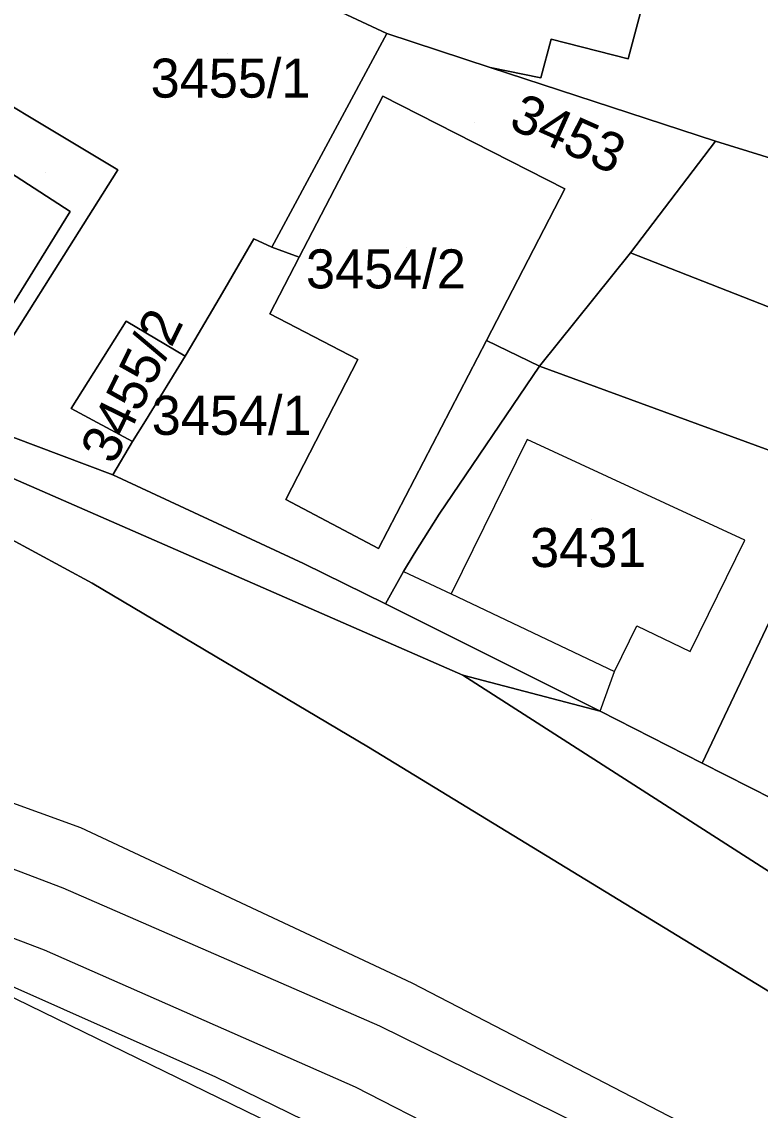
# Model space of a CAD drawing. Extents: x -262657 to -261595, y -1238015 to -1237156.
# Drawn here: x -262186.5 to -262148.7, y -1237601.5 to -1237545.8 of the extents above; entities that cross this region are included whole.
import ezdxf

# ---------------------------------------------------------------- set-up
doc = ezdxf.new("R2010")
doc.units = 0
for name, color, linetype in [('body_kn', 7, 'Continuous'), ('kladpar_druhypozemkov', 7, 'Continuous'), ('kladpar_hranice', 7, 'Continuous'), ('kladpar_parcelnecisla', 7, 'Continuous'), ('kladpar_plochy', 7, 'Continuous'), ('zappar_hrandruhpozemk', 7, 'Continuous')]:
    doc.layers.add(name, color=color, linetype=linetype)

msp = doc.modelspace()

# ---------------------------------------------------------------- linework, layer by layer
at = {"layer": 'body_kn'}
for p, q in [((-262167.81, -1237546.39), (-262167.81, -1237546.39)), ((-262167.81, -1237546.39), (-262167.81, -1237546.39)), ((-262159.39, -1237546.68), (-262159.39, -1237546.68)), ((-262155.46, -1237547.69), (-262155.46, -1237547.69)), ((-262162.52, -1237548.12), (-262162.52, -1237548.12)), ((-262159.92, -1237548.65), (-262159.92, -1237548.65)), ((-262168.02, -1237549.6), (-262168.02, -1237549.6)), ((-262150.98, -1237551.9), (-262150.98, -1237551.9)), ((-262150.98, -1237551.9), (-262150.98, -1237551.9)), ((-262181.58, -1237553.36), (-262181.58, -1237553.36)), ((-262158.69, -1237554.34), (-262158.69, -1237554.34)), ((-262184.02, -1237555.5), (-262184.02, -1237555.5)), ((-262174.62, -1237556.9), (-262174.62, -1237556.9)), ((-262173.7, -1237557.32), (-262173.7, -1237557.32)), ((-262172.3, -1237557.84), (-262172.3, -1237557.84)), ((-262155.34, -1237557.61), (-262155.34, -1237557.61)), ((-262176.21, -1237559.66), (-262176.21, -1237559.66)), ((-262173.8, -1237560.75), (-262173.8, -1237560.75)), ((-262173.8, -1237560.75), (-262173.8, -1237560.75)), ((-262181.14, -1237561.11), (-262181.14, -1237561.11)), ((-262177.64, -1237562.07), (-262177.64, -1237562.07)), ((-262162.71, -1237562.1), (-262162.71, -1237562.1)), ((-262178.13, -1237562.91), (-262178.13, -1237562.91)), ((-262169.29, -1237563.08), (-262169.29, -1237563.08)), ((-262159.99, -1237563.42), (-262159.99, -1237563.42)), ((-262159.99, -1237563.42), (-262159.99, -1237563.42)), ((-262183.96, -1237565.59), (-262183.96, -1237565.59)), ((-262180.16, -1237566.22), (-262180.16, -1237566.22)), ((-262180.82, -1237567.28), (-262180.82, -1237567.28)), ((-262180.82, -1237567.28), (-262180.82, -1237567.28)), ((-262160.62, -1237567.18), (-262160.62, -1237567.18)), ((-262181.83, -1237568.98), (-262181.83, -1237568.98)), ((-262181.83, -1237568.98), (-262181.83, -1237568.98)), ((-262172.98, -1237570.25), (-262172.98, -1237570.25)), ((-262165.13, -1237571), (-262165.13, -1237571)), ((-262149.48, -1237572.34), (-262149.48, -1237572.34)), ((-262168.23, -1237572.76), (-262168.23, -1237572.76)), ((-262166.4, -1237573.04), (-262166.4, -1237573.04)), ((-262172.07, -1237573.52), (-262172.07, -1237573.52)), ((-262172.07, -1237573.52), (-262172.07, -1237573.52)), ((-262166.95, -1237573.93), (-262166.95, -1237573.93)), ((-262166.95, -1237573.93), (-262166.95, -1237573.93)), ((-262182.88, -1237574.53), (-262182.88, -1237574.53)), ((-262164.52, -1237575.08), (-262164.52, -1237575.08)), ((-262164.52, -1237575.08), (-262164.52, -1237575.08)), ((-262167.88, -1237575.6), (-262167.88, -1237575.6)), ((-262155.02, -1237576.72), (-262155.02, -1237576.72)), ((-262152.28, -1237578.04), (-262152.28, -1237578.04)), ((-262156.15, -1237579.06), (-262156.15, -1237579.06)), ((-262163.92, -1237579.25), (-262163.92, -1237579.25)), ((-262156.89, -1237581.09), (-262156.89, -1237581.09)), ((-262156.89, -1237581.09), (-262156.89, -1237581.09)), ((-262168.75, -1237582.94), (-262168.75, -1237582.94)), ((-262151.67, -1237583.75), (-262151.67, -1237583.75)), ((-262151.67, -1237583.75), (-262151.67, -1237583.75)), ((-262183.48, -1237587.04), (-262183.48, -1237587.04)), ((-262184.37, -1237590.16), (-262184.37, -1237590.16)), ((-262185.35, -1237593.32), (-262185.35, -1237593.32)), ((-262166.53, -1237595), (-262166.53, -1237595)), ((-262168.16, -1237597.22), (-262168.16, -1237597.22)), ((-262176.55, -1237599.84), (-262176.55, -1237599.84)), ((-262169.42, -1237600.33), (-262169.42, -1237600.33))]:
    msp.add_line(p, q, dxfattribs=at)
at = {"layer": 'kladpar_druhypozemkov'}
for p, q in [((-262175.97, -1237547.4), (-262175.97, -1237547.4)), ((-262163.31, -1237550.96), (-262163.31, -1237550.96)), ((-262185.26, -1237553.48), (-262185.26, -1237553.48)), ((-262166.79, -1237557.34), (-262166.79, -1237557.34)), ((-262181.55, -1237563.61), (-262181.55, -1237563.61)), ((-262175.55, -1237564.94), (-262175.55, -1237564.94)), ((-262157.35, -1237571.27), (-262157.35, -1237571.27))]:
    msp.add_line(p, q, dxfattribs=at)
at = {"layer": 'kladpar_hranice'}
for p, q in [((-262156.89, -1237581.09), (-262163.92, -1237579.25)), ((-262163.92, -1237579.25), (-262156.89, -1237581.09))]:
    msp.add_line(p, q, dxfattribs=at)
for points in [[(-262167.81, -1237546.39), (-262172.13, -1237544.35), (-262172.1, -1237542.37), (-262164.03, -1237540.79), (-262161.8, -1237540.63), (-262154.15, -1237542.73), (-262155.46, -1237547.69), (-262159.39, -1237546.68), (-262159.92, -1237548.65), (-262162.52, -1237548.12), (-262167.81, -1237546.39)], [(-262181.83, -1237568.98), (-262189.59, -1237566.07), (-262181.58, -1237553.36), (-262191.37, -1237547.49), (-262190.39, -1237546.16), (-262190.29, -1237543.75), (-262185.04, -1237542.92), (-262172.97, -1237543.92), (-262172.13, -1237544.35), (-262167.81, -1237546.39), (-262173.7, -1237557.32), (-262174.62, -1237556.9), (-262176.21, -1237559.66), (-262177.64, -1237562.07), (-262178.13, -1237562.91), (-262181.14, -1237561.11), (-262183.96, -1237565.59), (-262180.82, -1237567.28), (-262181.83, -1237568.98)], [(-262150.98, -1237551.9), (-262162.52, -1237548.12), (-262159.92, -1237548.65), (-262159.39, -1237546.68), (-262155.46, -1237547.69), (-262154.15, -1237542.73), (-262146.14, -1237544.88), (-262127.87, -1237550.65), (-262129.29, -1237557.12), (-262089.88, -1237572.05), (-262091.36, -1237573.71), (-262114.93, -1237564.15), (-262131.62, -1237558.35), (-262139.63, -1237555.56), (-262146.25, -1237553.37), (-262150.98, -1237551.9)], [(-262159.99, -1237563.42), (-262162.71, -1237562.1), (-262158.69, -1237554.34), (-262168.02, -1237549.6), (-262172.3, -1237557.84), (-262173.7, -1237557.32), (-262167.81, -1237546.39), (-262162.52, -1237548.12), (-262150.98, -1237551.9), (-262155.34, -1237557.61), (-262159.99, -1237563.42)], [(-262189.59, -1237566.07), (-262190.37, -1237565.77), (-262200.33, -1237562.28), (-262199.41, -1237560.7), (-262198.38, -1237559.06), (-262189.46, -1237564.28), (-262184.02, -1237555.5), (-262190.48, -1237551.32), (-262189.4, -1237549.52), (-262191.8, -1237548.08), (-262191.37, -1237547.49), (-262181.58, -1237553.36), (-262189.59, -1237566.07)], [(-262284.57, -1237548.36), (-262280.56, -1237548.52), (-262275.85, -1237548.71), (-262269.47, -1237549.04), (-262241.76, -1237550.48), (-262238.68, -1237550.01), (-262238.76, -1237551.55), (-262233.07, -1237552.83), (-262232.32, -1237553), (-262224.57, -1237554.75), (-262222.49, -1237555.21), (-262210.43, -1237558.79), (-262200.33, -1237562.28), (-262190.37, -1237565.77), (-262189.59, -1237566.07), (-262181.83, -1237568.98), (-262172.07, -1237573.52)], [(-262193.47, -1237551.01), (-262191.8, -1237548.08), (-262189.4, -1237549.52), (-262190.48, -1237551.32), (-262184.02, -1237555.5), (-262189.46, -1237564.28), (-262198.38, -1237559.06), (-262193.47, -1237551.01)], [(-262173.8, -1237560.75), (-262172.3, -1237557.84), (-262168.02, -1237549.6), (-262158.69, -1237554.34), (-262162.71, -1237562.1), (-262168.23, -1237572.76), (-262172.98, -1237570.25), (-262169.29, -1237563.08), (-262173.8, -1237560.75)], [(-262163.92, -1237579.25), (-262199.34, -1237563.75), (-262233.3, -1237554.55), (-262250.47, -1237552.01), (-262250.41, -1237550.47), (-262269.27, -1237550.46)], [(-262269.27, -1237550.46), (-262250.41, -1237550.47), (-262250.47, -1237552.01), (-262233.3, -1237554.55), (-262199.34, -1237563.75), (-262163.92, -1237579.25)], [(-262021.16, -1237749.53), (-262023.07, -1237746.54), (-262062.32, -1237685.22), (-262069, -1237678.62), (-262099.55, -1237648.46), (-262139.84, -1237618.74), (-262199.91, -1237589.44), (-262214.16, -1237582.49), (-262218.71, -1237580.27), (-262317.63, -1237552.02)], [(-262300.35, -1237552.38), (-262266.92, -1237554.73), (-262245.89, -1237556.21), (-262215.1, -1237563.73), (-262191.61, -1237569.82), (-262182.88, -1237574.53), (-262168.75, -1237582.94), (-262143.5, -1237598.35), (-262084.62, -1237634.29), (-262085.82, -1237636.26), (-262084.08, -1237640.44), (-262083.99, -1237644.63), (-262083.24, -1237649.32), (-262080.3, -1237653.05), (-262067.75, -1237663.13)], [(-262134.31, -1237565.86), (-262155.34, -1237557.61), (-262150.98, -1237551.9), (-262146.25, -1237553.37), (-262139.63, -1237555.56), (-262131.62, -1237558.35), (-262134.31, -1237565.86)], [(-262143.5, -1237598.35), (-262168.75, -1237582.94), (-262182.88, -1237574.53), (-262191.61, -1237569.82), (-262215.1, -1237563.73), (-262245.89, -1237556.21), (-262266.92, -1237554.73)], [(-262180.82, -1237567.28), (-262180.16, -1237566.22), (-262178.13, -1237562.91), (-262177.64, -1237562.07), (-262176.21, -1237559.66), (-262174.62, -1237556.9), (-262173.7, -1237557.32), (-262172.3, -1237557.84), (-262173.8, -1237560.75), (-262169.29, -1237563.08), (-262172.98, -1237570.25), (-262168.23, -1237572.76), (-262162.71, -1237562.1), (-262159.99, -1237563.42), (-262165.13, -1237571), (-262166.4, -1237573.04), (-262166.95, -1237573.93), (-262167.88, -1237575.6), (-262172.07, -1237573.52), (-262181.83, -1237568.98), (-262180.82, -1237567.28)], [(-262131.32, -1237572.4), (-262132.54, -1237575.34), (-262139.2, -1237571.87), (-262146.03, -1237568.54), (-262159.99, -1237563.42), (-262155.34, -1237557.61), (-262134.31, -1237565.86), (-262133.96, -1237565.99), (-262135.76, -1237570.66), (-262131.32, -1237572.4)], [(-262180.82, -1237567.28), (-262183.96, -1237565.59), (-262181.14, -1237561.11), (-262178.13, -1237562.91), (-262180.16, -1237566.22), (-262180.82, -1237567.28)], [(-262151.67, -1237583.75), (-262156.89, -1237581.09), (-262167.88, -1237575.6), (-262166.95, -1237573.93), (-262166.4, -1237573.04), (-262165.13, -1237571), (-262159.99, -1237563.42), (-262146.03, -1237568.54), (-262139.2, -1237571.87), (-262132.54, -1237575.34), (-262135.03, -1237578.53), (-262135.63, -1237579.3), (-262141.27, -1237576.56), (-262146.92, -1237573.76), (-262151.67, -1237583.75)], [(-262172.07, -1237573.52), (-262167.88, -1237575.6), (-262156.89, -1237581.09)], [(-262141.98, -1237588.67), (-262151.67, -1237583.75), (-262146.92, -1237573.76), (-262141.27, -1237576.56), (-262135.63, -1237579.3), (-262138.4, -1237583.38), (-262140.61, -1237586.64), (-262141.98, -1237588.67)], [(-262143.5, -1237598.35), (-262144.39, -1237597.16), (-262143.52, -1237592.34), (-262163.92, -1237579.25)], [(-262163.92, -1237579.25), (-262143.52, -1237592.34), (-262144.39, -1237597.16), (-262143.5, -1237598.35)], [(-262156.89, -1237581.09), (-262151.67, -1237583.75), (-262141.98, -1237588.67), (-262129.36, -1237595.54)]]:
    msp.add_lwpolyline(points, dxfattribs=at)
at = {"layer": 'kladpar_plochy'}
for points in [[(-262167.81, -1237546.39), (-262172.13, -1237544.35), (-262172.1, -1237542.37), (-262164.03, -1237540.79), (-262161.8, -1237540.63), (-262154.15, -1237542.73), (-262155.46, -1237547.69), (-262159.39, -1237546.68), (-262159.92, -1237548.65), (-262162.52, -1237548.12)], [(-262181.83, -1237568.98), (-262189.59, -1237566.07), (-262181.58, -1237553.36), (-262191.37, -1237547.49), (-262190.39, -1237546.16), (-262190.29, -1237543.75), (-262185.04, -1237542.92), (-262172.97, -1237543.92), (-262172.13, -1237544.35), (-262167.81, -1237546.39), (-262173.7, -1237557.32), (-262174.62, -1237556.9), (-262176.21, -1237559.66), (-262177.64, -1237562.07), (-262178.13, -1237562.91), (-262181.14, -1237561.11), (-262183.96, -1237565.59), (-262180.82, -1237567.28)], [(-262150.98, -1237551.9), (-262162.52, -1237548.12), (-262159.92, -1237548.65), (-262159.39, -1237546.68), (-262155.46, -1237547.69), (-262154.15, -1237542.73), (-262146.14, -1237544.88), (-262127.87, -1237550.65), (-262129.29, -1237557.12), (-262089.88, -1237572.05), (-262091.36, -1237573.71), (-262114.93, -1237564.15), (-262131.62, -1237558.35), (-262139.63, -1237555.56), (-262146.25, -1237553.37)], [(-262159.99, -1237563.42), (-262162.71, -1237562.1), (-262158.69, -1237554.34), (-262168.02, -1237549.6), (-262172.3, -1237557.84), (-262173.7, -1237557.32), (-262167.81, -1237546.39), (-262162.52, -1237548.12), (-262150.98, -1237551.9), (-262155.34, -1237557.61)], [(-262269.27, -1237550.46), (-262250.41, -1237550.47), (-262250.47, -1237552.01), (-262233.3, -1237554.55), (-262199.34, -1237563.75), (-262163.92, -1237579.25), (-262143.52, -1237592.34), (-262144.39, -1237597.16), (-262143.5, -1237598.35), (-262168.75, -1237582.94), (-262182.88, -1237574.53), (-262191.61, -1237569.82), (-262215.1, -1237563.73), (-262245.89, -1237556.21), (-262266.92, -1237554.73), (-262290.64, -1237551.94), (-262300.35, -1237552.38), (-262305.92, -1237551.99), (-262307.78, -1237550.29), (-262309.76, -1237547.34), (-262302.19, -1237547.65), (-262284.57, -1237548.36)], [(-262189.59, -1237566.07), (-262190.37, -1237565.77), (-262200.33, -1237562.28), (-262199.41, -1237560.7), (-262198.38, -1237559.06), (-262189.46, -1237564.28), (-262184.02, -1237555.5), (-262190.48, -1237551.32), (-262189.4, -1237549.52), (-262191.8, -1237548.08), (-262191.37, -1237547.49), (-262181.58, -1237553.36)], [(-262193.47, -1237551.01), (-262191.8, -1237548.08), (-262189.4, -1237549.52), (-262190.48, -1237551.32), (-262184.02, -1237555.5), (-262189.46, -1237564.28), (-262198.38, -1237559.06)], [(-262173.8, -1237560.75), (-262172.3, -1237557.84), (-262168.02, -1237549.6), (-262158.69, -1237554.34), (-262162.71, -1237562.1), (-262168.23, -1237572.76), (-262172.98, -1237570.25), (-262169.29, -1237563.08)], [(-262134.31, -1237565.86), (-262155.34, -1237557.61), (-262150.98, -1237551.9), (-262146.25, -1237553.37), (-262139.63, -1237555.56), (-262131.62, -1237558.35)], [(-262180.82, -1237567.28), (-262180.16, -1237566.22), (-262178.13, -1237562.91), (-262177.64, -1237562.07), (-262176.21, -1237559.66), (-262174.62, -1237556.9), (-262173.7, -1237557.32), (-262172.3, -1237557.84), (-262173.8, -1237560.75), (-262169.29, -1237563.08), (-262172.98, -1237570.25), (-262168.23, -1237572.76), (-262162.71, -1237562.1), (-262159.99, -1237563.42), (-262165.13, -1237571), (-262166.4, -1237573.04), (-262166.95, -1237573.93), (-262167.88, -1237575.6), (-262172.07, -1237573.52), (-262181.83, -1237568.98)], [(-262131.32, -1237572.4), (-262132.54, -1237575.34), (-262139.2, -1237571.87), (-262146.03, -1237568.54), (-262159.99, -1237563.42), (-262155.34, -1237557.61), (-262134.31, -1237565.86), (-262133.96, -1237565.99), (-262135.76, -1237570.66)], [(-262180.82, -1237567.28), (-262183.96, -1237565.59), (-262181.14, -1237561.11), (-262178.13, -1237562.91), (-262180.16, -1237566.22)], [(-262151.67, -1237583.75), (-262156.89, -1237581.09), (-262167.88, -1237575.6), (-262166.95, -1237573.93), (-262166.4, -1237573.04), (-262165.13, -1237571), (-262159.99, -1237563.42), (-262146.03, -1237568.54), (-262139.2, -1237571.87), (-262132.54, -1237575.34), (-262135.03, -1237578.53), (-262135.63, -1237579.3), (-262141.27, -1237576.56), (-262146.92, -1237573.76)], [(-262141.98, -1237588.67), (-262151.67, -1237583.75), (-262146.92, -1237573.76), (-262141.27, -1237576.56), (-262135.63, -1237579.3), (-262138.4, -1237583.38), (-262140.61, -1237586.64)]]:
    msp.add_lwpolyline(points, close=True, dxfattribs=at)
for points in [[(-262269.47, -1237549.04), (-262241.76, -1237550.48), (-262238.68, -1237550.01), (-262238.76, -1237551.55), (-262233.07, -1237552.83), (-262232.32, -1237553), (-262224.57, -1237554.75), (-262222.49, -1237555.21), (-262210.43, -1237558.79), (-262200.33, -1237562.28), (-262190.37, -1237565.77), (-262189.59, -1237566.07), (-262181.83, -1237568.98), (-262172.07, -1237573.52), (-262167.88, -1237575.6), (-262156.89, -1237581.09), (-262163.92, -1237579.25), (-262199.34, -1237563.75), (-262233.3, -1237554.55), (-262250.47, -1237552.01), (-262250.41, -1237550.47), (-262269.27, -1237550.46)], [(-262021.16, -1237749.53), (-262023.07, -1237746.54), (-262062.32, -1237685.22), (-262069, -1237678.62), (-262099.55, -1237648.46), (-262139.84, -1237618.74), (-262199.91, -1237589.44), (-262214.16, -1237582.49), (-262218.71, -1237580.27), (-262317.63, -1237552.02)], [(-262300.35, -1237552.38), (-262266.92, -1237554.73), (-262245.89, -1237556.21), (-262215.1, -1237563.73), (-262191.61, -1237569.82), (-262182.88, -1237574.53), (-262168.75, -1237582.94), (-262143.5, -1237598.35), (-262084.62, -1237634.29), (-262085.82, -1237636.26), (-262084.08, -1237640.44), (-262083.99, -1237644.63), (-262083.24, -1237649.32), (-262080.3, -1237653.05), (-262067.75, -1237663.13)], [(-262027.48, -1237675.91), (-262038.27, -1237665.72), (-262070.96, -1237642.62), (-262072.51, -1237641.68), (-262084.62, -1237634.29), (-262143.5, -1237598.35), (-262144.39, -1237597.16), (-262143.52, -1237592.34), (-262163.92, -1237579.25), (-262156.89, -1237581.09), (-262151.67, -1237583.75), (-262141.98, -1237588.67), (-262129.36, -1237595.54), (-262088.7, -1237629.36), (-262054.48, -1237646.68), (-262047.43, -1237650.25), (-262043.99, -1237652.9), (-262021.27, -1237670.74)]]:
    msp.add_lwpolyline(points, dxfattribs=at)
at = {"layer": 'zappar_hrandruhpozemk'}
for p, q in [((-262160.62, -1237567.18), (-262164.52, -1237575.08)), ((-262149.48, -1237572.34), (-262160.62, -1237567.18)), ((-262166.95, -1237573.93), (-262164.52, -1237575.08)), ((-262164.52, -1237575.08), (-262156.15, -1237579.06)), ((-262166.53, -1237595), (-262148.99, -1237604.09)), ((-262149.67, -1237606.32), (-262168.16, -1237597.22)), ((-262169.42, -1237600.33), (-262151.15, -1237609.68))]:
    msp.add_line(p, q, dxfattribs=at)
for points in [[(-262168.16, -1237597.22), (-262184.37, -1237590.16), (-262195.46, -1237585.94), (-262210.94, -1237580.19), (-262225.73, -1237575.48), (-262243, -1237570.66), (-262262.57, -1237565.64)], [(-262242.52, -1237568.45), (-262225.04, -1237573.15), (-262210.05, -1237577.76), (-262193.89, -1237583.28), (-262183.48, -1237587.04), (-262166.53, -1237595)], [(-262156.89, -1237581.09), (-262156.15, -1237579.06), (-262155.02, -1237576.72), (-262152.28, -1237578.04), (-262149.48, -1237572.34)], [(-262214.16, -1237582.49), (-262196.75, -1237588.97), (-262185.35, -1237593.32), (-262169.42, -1237600.33)], [(-262169.06, -1237603.51), (-262176.55, -1237599.84), (-262199.91, -1237589.44)]]:
    msp.add_lwpolyline(points, dxfattribs=at)

# ---------------------------------------------------------------- texts
at = {"layer": 'kladpar_parcelnecisla'}
for s, p in [('3455/1', (-262179.893, -1237549.67)), ('3454/2', (-262171.944, -1237559.44)), ('3454/1', (-262179.838, -1237566.94)), ('3431', (-262160.475, -1237573.71))]:
    msp.add_text(s, height=2, dxfattribs=at).set_placement(p)
for s, rotation, p in [('3453', 336, (-262161.635, -1237551.203)), ('3455/2', 64, (-262181.769, -1237568.527))]:
    msp.add_text(s, height=2, rotation=rotation, dxfattribs=at).set_placement(p)

doc.saveas('drawing.dxf')
